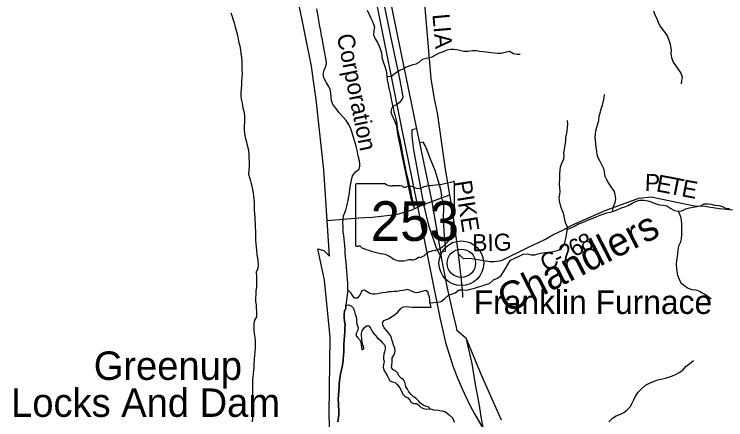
# Model space of a CAD drawing. Extents: x 1624196 to 2029251, y 146837 to 440034.
# Drawn here: x 1861002 to 1873487, y 232365 to 239492 of the extents above; entities that cross this region are included whole.
import ezdxf

# ---------------------------------------------------------------- set-up
doc = ezdxf.new("R2010")
doc.units = 0
for name, color, linetype in [('GM_X_County', 7, 'Continuous'), ('GM_X_County_Road', 7, 'Continuous'), ('GM_X_County_Road_Text', 7, 'Continuous'), ('GM_X_Hydro_Text', 7, 'Continuous'), ('GM_X_Interchange_Ramps', 7, 'Continuous'), ('GM_X_Major_River', 7, 'Continuous'), ('GM_X_Minor_River', 7, 'Continuous'), ('GM_X_Minor_River_Text', 7, 'Continuous'), ('GM_X_Rail_Line', 7, 'Continuous'), ('GM_X_Rail_Line_Text', 7, 'Continuous'), ('GM_X_State_Location', 7, 'Continuous'), ('GM_X_State_Route', 7, 'Continuous'), ('GM_X_State_Shield', 7, 'Continuous'), ('GM_X_Township', 7, 'Continuous'), ('GM_X_Township_Road', 7, 'Continuous'), ('GM_X_Unincorporated', 7, 'Continuous'), ('GM_X_Unincorporated_Location', 7, 'Continuous'), ('GM_X_Unincorporated_Text', 7, 'Continuous'), ('GM_X_US_Route', 7, 'Continuous')]:
    doc.layers.add(name, color=color, linetype=linetype)

msp = doc.modelspace()

# ---------------------------------------------------------------- linework, layer by layer
at = {"layer": 'GM_X_County'}
msp.add_lwpolyline([(1866564, 231274), (1866528, 232464), (1866546, 233815), (1866448, 234818), (1866330, 235372), (1866432, 235340), (1866534, 235240), (1866493, 235870), (1866436, 236758), (1866300, 237993), (1866255, 238319), (1866219, 238578), (1865861, 240357), (1865621, 241264), (1865417, 242067), (1864489, 244384), (1864191, 244913), (1864055, 245247), (1863597, 246098), (1863301, 246528), (1862715, 247271)], dxfattribs=at)
at = {"layer": 'GM_X_County_Road'}
for points in [[(1868646, 236320), (1868569, 236772), (1868430, 237762), (1868379, 238003), (1868315, 238365), (1868198, 239749)], [(1868800, 235284), (1868691, 236050), (1868646, 236320)], [(1868800, 235284), (1868877, 235198), (1868955, 235205), (1869030, 235201), (1869345, 235146), (1869430, 235144), (1869552, 235167), (1870012, 235391), (1870312, 235534), (1870450, 235615), (1870629, 235696), (1870787, 235787), (1871374, 236043), (1871961, 236257), (1872181, 236282), (1872940, 236126), (1873120, 236118), (1873370, 236080), (1873623, 236052)], [(1868859, 234706), (1868849, 234821), (1868800, 235284)], [(1868876, 234513), (1868871, 234575), (1868859, 234706)], [(1868927, 233803), (1869032, 233352), (1869083, 233021), (1869108, 232892)], [(1869108, 232892), (1869154, 232652), (1869201, 232345), (1869223, 232231)]]:
    msp.add_lwpolyline(points, dxfattribs=at)
at = {"layer": 'GM_X_Interchange_Ramps'}
for points in [[(1868060, 237479), (1867981, 237463), (1867979, 237355), (1867993, 237248), (1868010, 237112), (1868180, 236186), (1868186, 236147)], [(1868502, 236263), (1868498, 236286), (1868504, 236311), (1868502, 236330), (1868494, 236382), (1868463, 236494), (1868425, 236628), (1868387, 236745), (1868347, 236847), (1868296, 236976), (1868246, 237101), (1868215, 237183), (1868178, 237243), (1868112, 237230)], [(1868479, 235312), (1868567, 235328), (1868569, 235428), (1868551, 235592), (1868538, 235784), (1868536, 235958), (1868539, 236057), (1868538, 236120), (1868531, 236181), (1868518, 236223), (1868504, 236246), (1868502, 236263)]]:
    msp.add_lwpolyline(points, dxfattribs=at)
at = {"layer": 'GM_X_Major_River'}
msp.add_line((1866858, 234646), (1866823, 234380), dxfattribs=at)
for points in [[(1864805, 239517), (1864822, 239467), (1864840, 239413), (1864864, 239325), (1864879, 239266), (1864903, 239188), (1864919, 239126), (1864930, 239056), (1864944, 238990), (1864958, 238934), (1864971, 238862), (1864979, 238801), (1864989, 238739), (1864994, 238655), (1864996, 238591), (1864998, 238513), (1864999, 238453), (1864995, 238373), (1864991, 238319), (1864988, 238259), (1864984, 238173), (1864980, 238114), (1864977, 238056), (1864983, 238000), (1864999, 237928), (1865016, 237844), (1865030, 237788), (1865042, 237712), (1865041, 237598), (1865035, 237517), (1865036, 237453), (1865042, 237401), (1865056, 237325), (1865071, 237267), (1865085, 237213), (1865101, 237149), (1865111, 237089), (1865116, 237028), (1865120, 236960), (1865124, 236900), (1865123, 236834), (1865117, 236760), (1865114, 236682), (1865128, 236622), (1865146, 236566), (1865160, 236516), (1865169, 236465), (1865181, 236413), (1865193, 236353), (1865201, 236295), (1865206, 236241), (1865210, 236175), (1865212, 236121), (1865213, 236063), (1865217, 235979), (1865221, 235925), (1865226, 235874), (1865230, 235808), (1865232, 235746), (1865233, 235678), (1865235, 235570), (1865237, 235520), (1865240, 235466), (1865246, 235398), (1865254, 235344), (1865261, 235265), (1865269, 235205), (1865277, 235153), (1865285, 235093), (1865278, 235025), (1865246, 234961), (1865250, 234885), (1865251, 234813), (1865255, 234751), (1865253, 234693), (1865244, 234629), (1865240, 234573), (1865238, 234501), (1865237, 234442), (1865245, 234386), (1865249, 234328), (1865252, 234276), (1865254, 234226), (1865252, 234176), (1865216, 234114), (1865207, 234058), (1865207, 234002), (1865209, 233940)], [(1866843, 236144), (1866860, 236224), (1866872, 236288), (1866886, 236352), (1866893, 236414), (1866905, 236486), (1866920, 236578), (1866936, 236652), (1866988, 236720), (1867054, 236770), (1867065, 236822), (1867065, 236876), (1867055, 236940), (1867038, 237006), (1867024, 237074), (1867008, 237144), (1866997, 237196), (1866981, 237247), (1866961, 237309), (1866934, 237405), (1866910, 237479), (1866874, 237557), (1866829, 237626), (1866781, 237680), (1866698, 237765), (1866648, 237835), (1866594, 237905), (1866571, 237977), (1866563, 238037), (1866555, 238108), (1866544, 238168), (1866522, 238224), (1866480, 238284), (1866433, 238375), (1866423, 238441), (1866439, 238507), (1866462, 238561), (1866482, 238627), (1866476, 238687), (1866466, 238741), (1866453, 238813), (1866443, 238867), (1866427, 238941), (1866418, 238993), (1866410, 239048), (1866396, 239106), (1866379, 239200), (1866361, 239306), (1866348, 239380), (1866334, 239456), (1866311, 239585)], [(1866858, 234646), (1866856, 234716), (1866853, 234776), (1866849, 234826), (1866841, 234904), (1866836, 234978), (1866830, 235050), (1866824, 235137), (1866817, 235221), (1866809, 235297), (1866808, 235355), (1866804, 235421), (1866796, 235481), (1866792, 235537), (1866785, 235601), (1866775, 235663), (1866773, 235715), (1866772, 235766), (1866770, 235828), (1866772, 235886), (1866782, 235952), (1866807, 236022), (1866827, 236074), (1866843, 236144)], [(1867687, 233581), (1867679, 233625), (1867664, 233667), (1867636, 233759), (1867621, 233804), (1867603, 233848), (1867571, 233892), (1867532, 233934), (1867492, 233981), (1867475, 234021), (1867463, 234067), (1867487, 234111), (1867537, 234130), (1867579, 234146), (1867630, 234182), (1867676, 234208), (1867720, 234245), (1867756, 234287), (1867791, 234329), (1867835, 234352), (1867891, 234354), (1867933, 234350), (1867987, 234343), (1868033, 234343), (1868087, 234344), (1868175, 234344), (1868221, 234345), (1868269, 234345), (1868317, 234347), (1868305, 234393), (1868297, 234435), (1868294, 234469), (1868286, 234521), (1868272, 234565), (1868263, 234609), (1868227, 234636), (1868177, 234624), (1868093, 234601), (1868053, 234597), (1868011, 234607), (1867961, 234632), (1867911, 234652), (1867863, 234646), (1867819, 234635), (1867769, 234629), (1867717, 234622), (1867669, 234620), (1867619, 234616), (1867569, 234611), (1867527, 234603), (1867477, 234595), (1867429, 234590), (1867383, 234580), (1867337, 234575), (1867291, 234575), (1867243, 234585), (1867193, 234616), (1867150, 234646), (1867102, 234632), (1867083, 234591), (1867063, 234547), (1867017, 234505), (1866973, 234503), (1866943, 234544), (1866915, 234588), (1866887, 234618), (1866867, 234634), (1866858, 234646)], [(1866682, 232329), (1866693, 232405), (1866695, 232460), (1866698, 232536), (1866694, 232606), (1866690, 232658), (1866688, 232724), (1866693, 232792), (1866699, 232868), (1866704, 232938), (1866704, 232992), (1866708, 233046), (1866714, 233098), (1866729, 233166), (1866757, 233298), (1866768, 233360), (1866774, 233426), (1866780, 233497), (1866783, 233565), (1866783, 233623), (1866785, 233677), (1866794, 233773), (1866800, 233827), (1866804, 233925), (1866805, 233985), (1866807, 234039), (1866799, 234093), (1866790, 234163), (1866792, 234217), (1866800, 234273), (1866820, 234327), (1866823, 234380)], [(1866823, 234380), (1866820, 234327), (1866800, 234273), (1866792, 234217), (1866790, 234163), (1866799, 234093), (1866807, 234039), (1866805, 233985), (1866804, 233925), (1866800, 233827), (1866794, 233773), (1866785, 233677), (1866783, 233623), (1866783, 233565), (1866780, 233497), (1866774, 233426), (1866768, 233360), (1866757, 233298), (1866729, 233166), (1866714, 233098), (1866708, 233046), (1866704, 232992), (1866704, 232938), (1866699, 232868), (1866693, 232792), (1866688, 232724), (1866690, 232658), (1866694, 232606), (1866698, 232536), (1866695, 232460), (1866693, 232405), (1866682, 232329)], [(1866823, 234380), (1866868, 234388), (1866914, 234370), (1866951, 234333), (1866967, 234287), (1866979, 234241), (1866996, 234191), (1867010, 234149), (1867008, 234097), (1867011, 234047), (1867037, 233990), (1867030, 233940), (1867010, 233896), (1866996, 233850), (1867027, 233810), (1867063, 233774), (1867081, 233730), (1867088, 233680), (1867096, 233639), (1867103, 233595), (1867134, 233611), (1867128, 233655), (1867114, 233697), (1867109, 233741), (1867101, 233796), (1867093, 233838), (1867096, 233884), (1867108, 233930), (1867140, 233979), (1867181, 234017), (1867227, 234017), (1867256, 233977), (1867276, 233936), (1867298, 233894), (1867333, 233850), (1867377, 233805), (1867425, 233763), (1867460, 233725), (1867498, 233682), (1867508, 233652), (1867513, 233604), (1867499, 233560), (1867489, 233518), (1867480, 233472), (1867482, 233430), (1867492, 233388), (1867481, 233334), (1867477, 233288), (1867488, 233238), (1867518, 233192), (1867546, 233143), (1867567, 233097), (1867593, 233051), (1867641, 233031), (1867685, 233022), (1867718, 232994), (1867748, 232950), (1867778, 232903), (1867805, 232851), (1867829, 232807), (1867862, 232773), (1867910, 232750), (1867944, 232712), (1867964, 232668), (1868013, 232653), (1868059, 232649), (1868099, 232621), (1868143, 232584), (1868189, 232566), (1868238, 232553), (1868300, 232559), (1868265, 232593), (1868221, 232606), (1868175, 232622), (1868131, 232656), (1868096, 232697), (1868052, 232739), (1868008, 232771), (1867967, 232810), (1867927, 232856), (1867901, 232902), (1867876, 232947), (1867868, 232981), (1867858, 233027), (1867835, 233069), (1867791, 233099), (1867751, 233138), (1867732, 233182), (1867692, 233224), (1867648, 233243), (1867621, 233285), (1867629, 233327), (1867631, 233375), (1867632, 233415), (1867636, 233455), (1867660, 233501), (1867683, 233541), (1867687, 233581)], [(1865209, 233940), (1865213, 233884), (1865222, 233810), (1865228, 233754), (1865230, 233702), (1865227, 233633), (1865223, 233557), (1865219, 233499), (1865214, 233431), (1865208, 233347), (1865204, 233285), (1865199, 233233), (1865193, 233173), (1865189, 233117), (1865184, 233063), (1865180, 232967), (1865180, 232909), (1865183, 232833), (1865189, 232764), (1865197, 232698), (1865196, 232626), (1865194, 232576), (1865192, 232520), (1865187, 232460), (1865181, 232396), (1865177, 232328)], [(1865209, 233940), (1865213, 233884), (1865222, 233810), (1865228, 233754), (1865230, 233702), (1865227, 233633), (1865223, 233557), (1865219, 233499), (1865214, 233431), (1865208, 233347), (1865204, 233285), (1865199, 233233), (1865193, 233173), (1865189, 233117), (1865184, 233063), (1865180, 232967), (1865180, 232909), (1865183, 232833), (1865189, 232764), (1865197, 232698), (1865196, 232626), (1865194, 232576), (1865192, 232520), (1865187, 232460), (1865181, 232396), (1865177, 232328)]]:
    msp.add_lwpolyline(points, dxfattribs=at)
at = {"layer": 'GM_X_Minor_River'}
for points in [[(1867194, 239561), (1867261, 239424), (1867287, 239366), (1867306, 239316), (1867322, 239265), (1867314, 239203), (1867305, 239131), (1867334, 239057), (1867374, 238997), (1867407, 238928), (1867429, 238864), (1867446, 238814), (1867454, 238736), (1867475, 238658), (1867497, 238593), (1867522, 238519), (1867534, 238465), (1867541, 238395), (1867547, 238341), (1867558, 238287), (1867572, 238222), (1867583, 238170), (1867597, 238100), (1867608, 238034), (1867624, 237968), (1867635, 237918), (1867651, 237851), (1867664, 237785), (1867680, 237727), (1867693, 237675), (1867705, 237623), (1867714, 237569), (1867720, 237490), (1867731, 237440), (1867745, 237386), (1867758, 237336), (1867772, 237264), (1867787, 237196), (1867797, 237141), (1867808, 237063), (1867822, 237001), (1867833, 236949), (1867845, 236881), (1867856, 236823), (1867866, 236761), (1867879, 236702), (1867895, 236642), (1867912, 236572), (1867928, 236514), (1867945, 236438), (1867959, 236373), (1867966, 236313), (1867980, 236261), (1867997, 236193), (1868015, 236127)], [(1872221, 239551), (1872244, 239483), (1872272, 239429), (1872301, 239353), (1872333, 239286), (1872378, 239222), (1872422, 239165), (1872463, 239101), (1872487, 239039), (1872512, 238972), (1872520, 238922), (1872527, 238864), (1872523, 238800), (1872534, 238730), (1872567, 238652), (1872613, 238585), (1872648, 238535), (1872698, 238456), (1872721, 238392), (1872711, 238320), (1872704, 238270)], [(1867540, 238406), (1867575, 238397), (1867625, 238408), (1867693, 238460), (1867768, 238509), (1867824, 238535), (1867876, 238560), (1867948, 238590), (1868000, 238607), (1868052, 238621), (1868105, 238647), (1868167, 238700), (1868235, 238722), (1868285, 238731), (1868337, 238741), (1868387, 238775), (1868462, 238812), (1868534, 238835), (1868600, 238865), (1868662, 238876), (1868714, 238880), (1868766, 238874), (1868822, 238863), (1868892, 238841), (1868961, 238840), (1869042, 238853), (1869113, 238853), (1869165, 238843), (1869233, 238836), (1869291, 238832), (1869371, 238821), (1869429, 238816), (1869489, 238810), (1869545, 238810), (1869619, 238825), (1869691, 238840), (1869761, 238804), (1869828, 238793), (1869882, 238793)], [(1871511, 236028), (1871508, 236061), (1871518, 236113), (1871549, 236181), (1871559, 236249), (1871548, 236317), (1871532, 236375), (1871491, 236444), (1871431, 236528), (1871400, 236579), (1871374, 236643), (1871359, 236711), (1871353, 236761), (1871314, 236846), (1871275, 236914), (1871247, 236970), (1871232, 237024), (1871222, 237091), (1871215, 237155), (1871207, 237223), (1871196, 237331), (1871200, 237385), (1871209, 237441), (1871225, 237509), (1871258, 237625), (1871267, 237699), (1871289, 237779), (1871302, 237831), (1871322, 237893), (1871337, 237945), (1871353, 238023), (1871362, 238081)], [(1868300, 234422), (1868367, 234424), (1868431, 234430), (1868493, 234443), (1868556, 234497), (1868620, 234558), (1868674, 234574), (1868740, 234594), (1868811, 234651), (1868881, 234648), (1868950, 234644), (1869007, 234662), (1869077, 234679), (1869151, 234702), (1869211, 234720), (1869275, 234741), (1869341, 234761), (1869413, 234822), (1869480, 234856), (1869546, 234898), (1869588, 234963), (1869625, 235025), (1869661, 235093), (1869710, 235173), (1869784, 235208), (1869852, 235235), (1869935, 235273), (1870003, 235280), (1870071, 235266), (1870136, 235263), (1870189, 235279), (1870273, 235298), (1870323, 235304), (1870377, 235309), (1870427, 235317), (1870483, 235329), (1870533, 235342), (1870597, 235376), (1870649, 235437), (1870672, 235507), (1870688, 235573), (1870693, 235623), (1870705, 235687), (1870710, 235749), (1870680, 235816), (1870665, 235872), (1870649, 235948), (1870634, 236006), (1870607, 236080), (1870589, 236139), (1870568, 236215), (1870564, 236269), (1870576, 236323), (1870581, 236385), (1870573, 236439), (1870570, 236505), (1870575, 236609), (1870573, 236689), (1870580, 236753), (1870586, 236813), (1870617, 236885), (1870645, 236949), (1870652, 237001), (1870648, 237059), (1870655, 237109), (1870665, 237165), (1870676, 237223), (1870682, 237275), (1870682, 237327), (1870693, 237379), (1870705, 237431), (1870710, 237503), (1870714, 237557), (1870711, 237625)], [(1870707, 235709), (1870768, 235739), (1870834, 235770), (1870902, 235806), (1870956, 235827), (1871016, 235851), (1871091, 235882), (1871163, 235910), (1871227, 235935), (1871285, 235961), (1871349, 235986), (1871403, 236002), (1871463, 236012), (1871532, 236035), (1871582, 236057), (1871658, 236090), (1871714, 236110), (1871776, 236133), (1871844, 236169), (1871913, 236208), (1871979, 236226), (1872051, 236223), (1872122, 236211), (1872176, 236196), (1872248, 236166), (1872320, 236143), (1872394, 236134), (1872454, 236124), (1872523, 236079), (1872587, 236041), (1872651, 236032), (1872717, 236040), (1872789, 236073), (1872849, 236089), (1872913, 236102), (1872977, 236114), (1873043, 236125), (1873109, 236161), (1873179, 236158), (1873233, 236156), (1873287, 236137), (1873363, 236129), (1873429, 236116), (1873483, 236086), (1873550, 236077)], [(1872647, 236033), (1872661, 236008), (1872692, 235940), (1872703, 235868), (1872711, 235804), (1872708, 235736), (1872708, 235682), (1872709, 235617), (1872705, 235545), (1872690, 235477), (1872660, 235416), (1872647, 235348), (1872643, 235286), (1872632, 235232), (1872622, 235164), (1872619, 235092), (1872621, 235036), (1872626, 234973), (1872642, 234909), (1872667, 234839), (1872701, 234771), (1872772, 234712), (1872826, 234680), (1872892, 234657), (1872960, 234647), (1873025, 234628), (1873097, 234583), (1873167, 234545), (1873234, 234492)], [(1871434, 232332), (1871501, 232392), (1871567, 232433), (1871639, 232465), (1871700, 232496), (1871752, 232532), (1871810, 232595), (1871845, 232655), (1871873, 232715), (1871900, 232767), (1871952, 232849), (1872011, 232910), (1872081, 232974), (1872151, 233011), (1872221, 233041), (1872274, 233060), (1872378, 233084), (1872432, 233099), (1872498, 233119), (1872554, 233140), (1872604, 233162), (1872672, 233199), (1872735, 233239), (1872789, 233303), (1872857, 233352), (1872922, 233406)], [(1868300, 232559), (1868366, 232538), (1868442, 232534), (1868504, 232523), (1868570, 232505), (1868635, 232452), (1868697, 232396), (1868720, 232325)]]:
    msp.add_lwpolyline(points, dxfattribs=at)
at = {"layer": 'GM_X_Rail_Line'}
msp.add_lwpolyline([(1865902, 246960), (1866043, 246254), (1866226, 245339), (1866698, 242981), (1866812, 242410), (1867003, 241461), (1867225, 240350), (1867353, 239710), (1867794, 237520), (1867975, 236633), (1868094, 236028), (1868475, 234135), (1868514, 233956), (1868571, 233724), (1868638, 233498), (1868700, 233315), (1868774, 233116), (1868864, 232907), (1868944, 232733), (1868998, 232624), (1869078, 232472), (1869206, 232247)], dxfattribs=at)
at = {"layer": 'GM_X_State_Route'}
for points in [[(1868186, 236147), (1868329, 236201), (1868502, 236263), (1868646, 236320)], [(1868065, 236094), (1868186, 236147), (1868272, 235784), (1868405, 235388), (1868494, 235219)], [(1866493, 235870), (1867050, 235917), (1867282, 235925), (1867696, 235973), (1867769, 235990), (1867983, 236057), (1868026, 236076), (1868065, 236094)]]:
    msp.add_lwpolyline(points, dxfattribs=at)
at = {"layer": 'GM_X_State_Shield'}
for p, q in [((1866988, 236491), (1866988, 235435)), ((1867514, 236509), (1867005, 236509)), ((1868728, 235983), (1868728, 236536)), ((1868728, 235983), (1868728, 235983))]:
    msp.add_line(p, q, dxfattribs=at)
for centre, major_axis, start_param, end_param in [((1867008, 236494), (20.2, 0), 1.712693, 3.28349), ((1867636, 236632), (196, 0), 4.042523, 4.731795), ((1867701, 235916), (702, 0), 1.404758, 1.657858), ((1868343, 236187), (371, 0), 1.699011, 2.107814), ((1868108, 237950), (1845, 0), 4.814394, 5.042369), ((1868709, 236538), (19.4, 0), 6.141152, 7.989035), ((1867860, 236499), (56.4, 0), 3.836095, 5.185415), ((1867943, 236377), (117, 0), 0.950623, 2.079405), ((1868094, 236544), (141, 0), 4.081561, 5.145723), ((1868707, 235981), (20.7, 0), 5.05454, 6.418171), ((1868723, 235942), (30, 0), 1.883978, 3.671073), ((1868533, 235872), (180, 0), 5.934695, 6.695948), ((1868211, 235681), (462, 0), 5.101752, 6.440018), ((1868797, 235752), (131, 0), 2.387724, 3.262537), ((1867008, 235432), (20.3, 0), 3.00124, 4.508301), ((1867011, 235540), (155, 0), 4.665946, 4.897461), ((1867043, 235374), (56, 0), 0.519207, 1.627899), ((1867749, 236323), (1333, 0), 4.195997, 4.488961), ((1867352, 234960), (417, 0), 0.823519, 1.323587), ((1868086, 235332), (149, 0), 4.937069, 5.64225), ((1868406, 235138), (253, 0), 1.647645, 2.488434), ((1867803, 235368), (265, 0), 4.026481, 4.996735), ((1867956, 235003), (217, 0), 1.495662, 1.94098), ((1867975, 235289), (141, 0), 4.691044, 5.507374), ((1868103, 235187), (39.7, 0), 1.147584, 2.315152)]:
    msp.add_ellipse(centre, major_axis=major_axis, ratio=0.8, start_param=start_param, end_param=end_param, dxfattribs=at)
at = {"layer": 'GM_X_Township'}
msp.add_lwpolyline([(1866564, 231274), (1866528, 232464), (1866546, 233815), (1866448, 234818), (1866330, 235372), (1866432, 235340), (1866534, 235240), (1866493, 235870), (1866436, 236758), (1866300, 237993), (1866255, 238319), (1866219, 238578), (1865861, 240357), (1865621, 241264), (1865417, 242067), (1864489, 244384), (1864191, 244913), (1864055, 245247), (1863597, 246098), (1863301, 246528), (1862715, 247271)], dxfattribs=at)
at = {"layer": 'GM_X_Township_Road'}
for points in [[(1867755, 238418), (1867606, 239131), (1866702, 243591), (1866247, 245937), (1865461, 249817), (1865302, 250483), (1865292, 250528), (1865260, 250698)], [(1868026, 236076), (1867965, 236253), (1867811, 237016), (1867735, 237393), (1867715, 237523), (1867681, 237613), (1867631, 237716), (1867618, 237763), (1867625, 237836), (1867645, 237873), (1867728, 237920), (1867781, 237960), (1867811, 237996), (1867825, 238043), (1867805, 238176), (1867755, 238418)]]:
    msp.add_lwpolyline(points, dxfattribs=at)
at = {"layer": 'GM_X_Unincorporated'}
for radius in [393, 249]:
    msp.add_circle((1868847, 235116), radius, dxfattribs=at)
at = {"layer": 'GM_X_Unincorporated_Location'}
msp.add_line((1868847, 235116), (1868847, 235116), dxfattribs=at)
at = {"layer": 'GM_X_US_Route'}
for points in [[(1865849, 248501), (1866230, 246541), (1866636, 244514), (1866716, 244099), (1867115, 242099), (1867263, 241378), (1867421, 240623), (1867565, 239920), (1867645, 239505), (1868060, 237479), (1868112, 237230), (1868324, 236224)], [(1868324, 236224), (1868329, 236201), (1868359, 236021)], [(1868359, 236021), (1868479, 235312), (1868494, 235219)], [(1868494, 235219), (1868601, 234681), (1868705, 234208), (1868754, 233992)], [(1868754, 233992), (1868764, 233947), (1868927, 233803), (1869194, 233155), (1869453, 232576), (1869547, 232365)]]:
    msp.add_lwpolyline(points, dxfattribs=at)

# ---------------------------------------------------------------- texts
at = {"layer": 'GM_X_County_Road_Text'}
for s, rotation, p in [('L', 275.0121, (1868339, 239489)), ('I', 275.0022, (1868359, 239265)), ('A', 275.0043, (1868369, 239143)), ('P', 357.7591, (1872062, 236389)), ('E', 349.5083, (1872253, 236382)), ('T', 348.5787, (1872472, 236342)), ('PIKE', 278.9564, (1868728, 236551)), ('E', 349.3534, (1872697, 236296)), ('BIG', 1.219, (1869040, 235325)), ('8', 25.3454, (1870989, 235303)), ('6', 28.7019, (1870831, 235216)), ('2', 26.8758, (1870657, 235128)), ('C', 26.5825, (1870325, 234962)), ('-', 26.6387, (1870546, 235072))]:
    msp.add_text(s, height=300, rotation=rotation, dxfattribs=at).set_placement(p)
at = {"layer": 'GM_X_Hydro_Text'}
for s, height, p in [('Greenup', 500, (1862397, 233066)), ('Locks And Dam', 499.98, (1860947, 232417))]:
    msp.add_text(s, height=height, rotation=359.9982, dxfattribs=at).set_placement(p)
at = {"layer": 'GM_X_Minor_River_Text'}
msp.add_text('Chandlers', height=500, rotation=26.9972, dxfattribs=at).set_placement((1869648, 234225))
at = {"layer": 'GM_X_Rail_Line_Text'}
msp.add_text('Corporation', height=299, rotation=281.3936, dxfattribs=at).set_placement((1866660, 239119))
at = {"layer": 'GM_X_State_Location'}
for s in ['s', 'r']:
    msp.add_text(s, height=1, dxfattribs=at).set_placement((1867838, 235893))
msp.add_text('253', height=1, rotation=0, dxfattribs=at).set_placement((1867485, 235820))
at = {"layer": 'GM_X_State_Shield'}
msp.add_text('253', height=696.1, dxfattribs=at).set_placement((1867255, 235509))
at = {"layer": 'GM_X_Unincorporated_Text'}
msp.add_text('Franklin Furnace', height=417, rotation=0, dxfattribs=at).set_placement((1869065, 234225))

doc.saveas('drawing.dxf')
